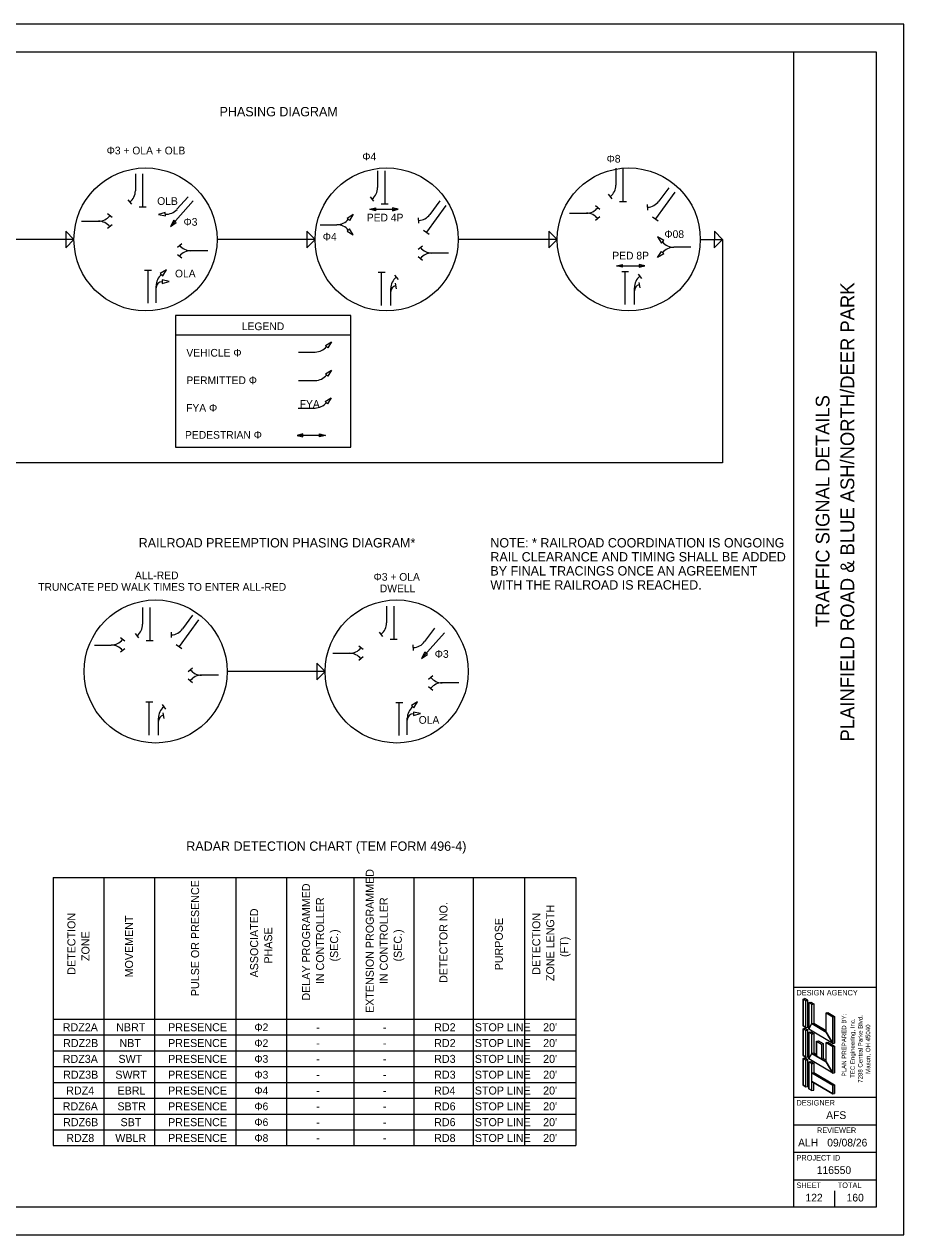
# Model space of a CAD drawing. Extents: x 0 to 34, y 0 to 22.
# Drawn here: x 18.02 to 34, y 0 to 22 of the extents above; entities that cross this region are included whole.
import ezdxf

# ---------------------------------------------------------------- set-up
doc = ezdxf.new("R2010")
doc.units = 0
for name, color, linetype in [('Default', 7, 'Continuous'), ('SG_P_Text', 7, 'Continuous'), ('SH_Border', 7, 'Continuous'), ('SH_Cut_Line', 7, 'Continuous'), ('SH_Data', 7, 'Continuous'), ('SH_Text', 7, 'Continuous')]:
    doc.layers.add(name, color=color, linetype=linetype)

msp = doc.modelspace()

# ---------------------------------------------------------------- linework, layer by layer
at = {"layer": 'SG_P_Text'}
for p, q in [((18.923, 18.089), (17.142, 18.089)), ((23.303, 18.089), (21.522, 18.089)), ((27.704, 18.089), (25.924, 18.089)), ((20.765, 16.356), (23.956, 16.356)), ((23.487, 10.237), (21.706, 10.237)), ((18.544, 6.492), (28.044, 6.492)), ((18.544, 6.492), (18.544, 1.62)), ((19.464, 6.492), (19.464, 1.62)), ((20.384, 6.492), (20.384, 1.62)), ((21.864, 6.492), (21.864, 1.62)), ((22.784, 6.492), (22.784, 1.62)), ((24.005, 6.492), (24.005, 1.62)), ((25.098, 6.492), (25.098, 1.62)), ((26.175, 6.492), (26.175, 1.62)), ((27.11, 6.492), (27.11, 1.62)), ((28.044, 6.492), (28.044, 1.62)), ((18.544, 3.92), (28.044, 3.92)), ((18.544, 3.632), (28.044, 3.632)), ((18.544, 3.345), (28.044, 3.345)), ((18.544, 3.057), (28.044, 3.057)), ((18.544, 2.77), (28.044, 2.77)), ((18.544, 2.482), (28.044, 2.482)), ((18.544, 2.195), (28.044, 2.195)), ((18.544, 1.907), (28.044, 1.907)), ((18.544, 1.62), (28.044, 1.62))]:
    msp.add_line(p, q, dxfattribs=at)
msp.add_lwpolyline([(30.303, 18.089), (30.709, 18.089), (30.709, 14.028), (14.543, 14.028), (14.137, 14.028), (14.137, 18.089), (14.543, 18.089)], dxfattribs=at)
for points in [[(18.923, 18.089), (18.772, 18.241), (18.772, 17.938)], [(23.303, 18.089), (23.152, 18.241), (23.152, 17.938)], [(27.704, 18.089), (27.552, 18.241), (27.552, 17.938)], [(30.709, 18.089), (30.558, 18.241), (30.557, 17.938)], [(23.956, 16.706), (20.767, 16.706), (20.767, 14.311), (23.956, 14.311)], [(23.487, 10.237), (23.336, 10.388), (23.335, 10.085)]]:
    msp.add_lwpolyline(points, close=True, dxfattribs=at)
for centre in [(20.223, 18.089), (24.603, 18.089), (29.003, 18.089), (20.406, 10.237), (24.787, 10.237)]:
    msp.add_circle(centre, 1.3, dxfattribs=at)
at = {"layer": 'SH_Border'}
for p, q in [((32, 0.5), (32, 21.5)), ((32, 4.5), (33.5, 4.5)), ((32, 2.5), (33.5, 2.5)), ((32, 2), (33.5, 2)), ((32, 1.5), (33.5, 1.5)), ((32, 1), (33.5, 1))]:
    msp.add_line(p, q, dxfattribs=at)
msp.add_lwpolyline([(1.5, 21.5), (33.5, 21.5), (33.5, 0.5), (1.5, 0.5)], close=True, dxfattribs=at)
at = {"layer": 'SH_Cut_Line'}
msp.add_lwpolyline([(0, 0), (34, 0), (34, 22), (0, 22)], close=True, dxfattribs=at)
at = {"layer": 'SH_Data'}
for p, q in [((32.75, 3.5), (32.75, 3.5)), ((32.375, 0.675), (32.375, 0.675)), ((32.75, 0.5), (32.75, 0.8))]:
    msp.add_line(p, q, dxfattribs=at)
at = {"layer": 'SH_Text'}
for p, q in [((28.768, 19.381), (28.768, 19.076)), ((28.898, 19.381), (28.898, 18.78)), ((20.039, 19.279), (20.039, 18.974)), ((20.168, 19.279), (20.168, 18.679)), ((24.439, 19.337), (24.439, 19.031)), ((24.569, 19.337), (24.569, 18.736)), ((29.84, 18.948), (29.486, 18.463)), ((29.73, 19.029), (29.549, 18.782)), ((19.972, 18.727), (19.908, 18.807)), ((20.675, 18.325), (21.09, 18.789)), ((20.998, 18.863), (20.794, 18.636)), ((24.372, 18.785), (24.308, 18.865)), ((24.505, 18.736), (24.632, 18.736)), ((25.68, 18.708), (25.326, 18.222)), ((25.569, 18.788), (25.389, 18.542)), ((28.701, 18.829), (28.637, 18.909)), ((28.834, 18.78), (28.961, 18.78)), ((29.35, 18.623), (29.345, 18.725)), ((19.614, 18.487), (19.534, 18.551)), ((20.105, 18.679), (20.232, 18.679)), ((24.3, 18.636), (24.813, 18.636)), ((25.189, 18.382), (25.185, 18.484)), ((27.927, 18.566), (28.233, 18.566)), ((27.927, 18.566), (28.233, 18.566)), ((28.479, 18.633), (28.4, 18.697)), ((28.479, 18.499), (28.4, 18.435)), ((29.435, 18.5), (29.538, 18.426)), ((19.062, 18.42), (19.368, 18.42)), ((19.062, 18.42), (19.368, 18.42)), ((19.614, 18.353), (19.534, 18.289)), ((23.395, 18.357), (23.701, 18.357)), ((23.395, 18.357), (23.701, 18.357)), ((25.275, 18.26), (25.377, 18.185)), ((20.801, 17.95), (20.88, 18.014)), ((21.352, 17.883), (21.047, 17.883)), ((21.352, 17.883), (21.047, 17.883)), ((25.178, 17.909), (25.258, 17.973)), ((25.73, 17.842), (25.424, 17.842)), ((25.73, 17.842), (25.424, 17.842)), ((30.129, 17.946), (29.823, 17.946)), ((30.129, 17.946), (29.823, 17.946)), ((20.801, 17.816), (20.88, 17.752)), ((25.178, 17.776), (25.258, 17.711)), ((28.781, 17.61), (29.294, 17.61)), ((20.204, 17.529), (20.331, 17.529)), ((20.268, 16.928), (20.268, 17.529)), ((24.45, 17.491), (24.577, 17.491)), ((24.513, 16.89), (24.513, 17.491)), ((24.747, 17.442), (24.811, 17.362)), ((28.875, 17.507), (29.001, 17.507)), ((28.938, 16.907), (28.938, 17.507)), ((29.172, 17.459), (29.236, 17.379)), ((20.414, 16.937), (20.414, 17.242)), ((20.415, 17.13), (20.415, 17.207)), ((24.68, 16.89), (24.68, 17.196)), ((24.761, 17.293), (24.778, 17.192)), ((29.105, 16.907), (29.105, 17.212)), ((29.185, 17.309), (29.203, 17.209)), ((24.681, 17.098), (24.681, 17.14)), ((29.105, 17.114), (29.105, 17.157)), ((23.001, 16.043), (23.307, 16.043)), ((23.001, 15.526), (23.307, 15.526)), ((22.996, 15.025), (23.302, 15.025)), ((23.49, 14.528), (22.977, 14.528)), ((20.17, 11.401), (20.17, 11.095)), ((20.3, 11.401), (20.3, 10.8)), ((21.077, 11.258), (20.897, 11.011)), ((24.602, 11.427), (24.602, 11.121)), ((24.732, 11.427), (24.732, 10.826)), ((21.188, 11.177), (20.834, 10.692)), ((25.472, 11.027), (25.292, 10.78)), ((19.845, 10.785), (19.766, 10.849)), ((20.103, 10.849), (20.039, 10.928)), ((20.236, 10.8), (20.363, 10.8)), ((20.697, 10.852), (20.693, 10.954)), ((24.535, 10.875), (24.471, 10.954)), ((24.669, 10.826), (24.796, 10.826)), ((25.239, 10.472), (25.654, 10.937)), ((19.293, 10.718), (19.599, 10.718)), ((19.293, 10.718), (19.599, 10.718)), ((19.845, 10.651), (19.766, 10.587)), ((20.782, 10.729), (20.885, 10.654)), ((23.626, 10.568), (23.931, 10.568)), ((23.626, 10.568), (23.931, 10.568)), ((24.178, 10.635), (24.098, 10.699)), ((25.093, 10.62), (25.088, 10.722)), ((24.178, 10.501), (24.098, 10.437)), ((20.995, 10.237), (21.075, 10.301)), ((21.547, 10.17), (21.242, 10.17)), ((21.547, 10.17), (21.242, 10.17)), ((25.364, 10.098), (25.444, 10.162)), ((20.995, 10.103), (21.075, 10.039)), ((25.364, 9.964), (25.444, 9.9)), ((25.916, 10.031), (25.611, 10.031)), ((25.916, 10.031), (25.611, 10.031)), ((20.227, 9.683), (20.354, 9.683)), ((20.291, 9.082), (20.291, 9.683)), ((20.524, 9.634), (20.588, 9.554)), ((20.538, 9.485), (20.556, 9.384)), ((24.768, 9.676), (24.895, 9.676)), ((24.831, 9.076), (24.831, 9.676)), ((20.457, 9.082), (20.457, 9.388)), ((20.458, 9.29), (20.458, 9.332)), ((24.978, 9.084), (24.978, 9.389)), ((24.979, 9.277), (24.979, 9.355)), ((32.169, 4.285), (32.201, 4.294)), ((32.169, 3.799), (32.169, 4.285)), ((32.223, 4.253), (32.169, 4.285)), ((32.255, 4.261), (32.201, 4.294)), ((32.223, 4.253), (32.255, 4.261)), ((32.223, 3.767), (32.223, 4.253)), ((32.255, 3.775), (32.255, 4.261)), ((32.277, 4.221), (32.309, 4.229)), ((32.331, 4.188), (32.277, 4.221)), ((32.277, 3.735), (32.277, 4.221)), ((32.309, 4.229), (32.363, 4.196)), ((32.331, 4.188), (32.363, 4.196)), ((32.331, 3.837), (32.331, 4.188)), ((32.363, 4.196), (32.363, 3.845)), ((32.587, 4.034), (32.62, 4.042)), ((32.587, 3.683), (32.587, 4.034)), ((32.709, 3.961), (32.587, 4.034)), ((32.62, 4.042), (32.741, 3.97)), ((32.709, 3.961), (32.741, 3.97)), ((32.709, 3.475), (32.709, 3.961)), ((32.741, 3.97), (32.741, 3.484)), ((32.223, 3.767), (32.169, 3.799)), ((32.169, 3.745), (32.201, 3.754)), ((32.169, 3.259), (32.169, 3.745)), ((32.223, 3.713), (32.169, 3.745)), ((32.255, 3.722), (32.201, 3.754)), ((32.223, 3.767), (32.255, 3.775)), ((32.331, 3.837), (32.363, 3.845)), ((32.587, 3.683), (32.331, 3.837)), ((32.363, 3.845), (32.587, 3.711)), ((32.223, 3.713), (32.255, 3.722)), ((32.223, 3.227), (32.223, 3.713)), ((32.255, 3.236), (32.255, 3.722)), ((32.709, 3.475), (32.277, 3.735)), ((32.277, 3.681), (32.309, 3.689)), ((32.277, 3.195), (32.277, 3.681)), ((32.331, 3.648), (32.277, 3.681)), ((32.309, 3.689), (32.363, 3.656)), ((32.331, 3.648), (32.363, 3.656)), ((32.331, 3.297), (32.331, 3.648)), ((32.363, 3.656), (32.363, 3.305)), ((32.415, 3.519), (32.448, 3.527)), ((32.448, 3.527), (32.535, 3.474)), ((32.331, 3.297), (32.363, 3.305)), ((32.363, 3.305), (32.415, 3.274)), ((32.415, 3.519), (32.415, 3.247)), ((32.415, 3.519), (32.503, 3.466)), ((32.503, 3.466), (32.535, 3.474)), ((32.503, 3.466), (32.503, 3.194)), ((32.535, 3.474), (32.535, 3.202)), ((32.587, 3.494), (32.62, 3.502)), ((32.587, 3.143), (32.587, 3.494)), ((32.709, 3.421), (32.587, 3.494)), ((32.62, 3.502), (32.741, 3.43)), ((32.709, 3.475), (32.741, 3.484)), ((32.709, 3.421), (32.741, 3.43)), ((32.709, 2.935), (32.709, 3.421)), ((32.741, 3.43), (32.741, 2.944)), ((32.223, 3.227), (32.169, 3.259)), ((32.169, 3.205), (32.201, 3.215)), ((32.169, 2.719), (32.169, 3.205)), ((32.223, 3.173), (32.169, 3.205)), ((32.255, 3.181), (32.201, 3.215)), ((32.222, 3.173), (32.255, 3.181)), ((32.223, 3.227), (32.255, 3.236)), ((32.223, 2.687), (32.223, 3.173)), ((32.255, 2.695), (32.255, 3.181)), ((32.709, 2.935), (32.277, 3.195)), ((32.277, 3.141), (32.309, 3.151)), ((32.331, 3.108), (32.277, 3.141)), ((32.277, 2.655), (32.277, 3.141)), ((32.309, 3.151), (32.363, 3.116)), ((32.415, 3.247), (32.331, 3.297)), ((32.331, 3.108), (32.363, 3.116)), ((32.331, 2.944), (32.331, 3.108)), ((32.363, 3.116), (32.363, 2.952)), ((32.503, 3.194), (32.535, 3.202)), ((32.587, 3.143), (32.503, 3.194)), ((32.535, 3.202), (32.587, 3.171)), ((32.331, 2.944), (32.363, 2.952)), ((32.331, 2.944), (32.709, 2.717)), ((32.363, 2.952), (32.741, 2.725)), ((32.709, 2.935), (32.741, 2.944)), ((32.223, 2.687), (32.169, 2.719)), ((32.223, 2.687), (32.255, 2.695)), ((32.331, 2.622), (32.277, 2.655)), ((32.331, 2.787), (32.709, 2.56)), ((32.331, 2.622), (32.331, 2.787)), ((32.363, 2.63), (32.363, 2.767)), ((32.709, 2.717), (32.741, 2.725)), ((32.709, 2.56), (32.709, 2.717)), ((32.741, 2.725), (32.741, 2.568)), ((32.331, 2.622), (32.363, 2.63)), ((32.709, 2.56), (32.741, 2.568))]:
    msp.add_line(p, q, dxfattribs=at)
for points in [[(20.581, 18.579), (20.458, 18.54), (20.585, 18.516)], [(23.885, 18.478), (23.996, 18.545), (23.929, 18.434)], [(24.404, 18.61), (24.3, 18.636), (24.404, 18.662)], [(24.709, 18.61), (24.813, 18.636), (24.709, 18.662)], [(20.735, 18.439), (20.675, 18.325), (20.782, 18.397)], [(23.885, 18.236), (23.996, 18.17), (23.929, 18.28)], [(29.639, 18.067), (29.528, 18.134), (29.595, 18.023)], [(29.639, 17.825), (29.528, 17.759), (29.595, 17.87)], [(28.885, 17.584), (28.781, 17.61), (28.885, 17.636)], [(29.19, 17.584), (29.294, 17.61), (29.19, 17.636)], [(20.535, 17.427), (20.602, 17.537), (20.491, 17.471)], [(20.528, 17.29), (20.652, 17.324), (20.526, 17.352)], [(23.491, 16.164), (23.602, 16.23), (23.535, 16.12)], [(23.491, 15.647), (23.602, 15.713), (23.535, 15.603)], [(23.486, 15.146), (23.597, 15.212), (23.53, 15.102)], [(23.081, 14.554), (22.977, 14.528), (23.081, 14.502)], [(23.386, 14.554), (23.49, 14.528), (23.386, 14.502)], [(25.299, 10.586), (25.239, 10.472), (25.346, 10.544)], [(25.099, 9.574), (25.165, 9.685), (25.055, 9.618)], [(25.091, 9.437), (25.216, 9.472), (25.09, 9.5)], [(32.169, 3.799), (32.223, 3.767), (32.223, 4.253), (32.169, 4.285)], [(32.277, 3.735), (32.331, 3.837), (32.331, 4.188), (32.277, 4.221)], [(32.709, 3.475), (32.587, 3.683), (32.587, 4.034), (32.709, 3.961)], [(32.169, 3.259), (32.223, 3.227), (32.223, 3.713), (32.169, 3.745)], [(32.277, 3.735), (32.331, 3.837), (32.587, 3.683), (32.709, 3.475)], [(32.277, 3.195), (32.331, 3.297), (32.331, 3.648), (32.277, 3.681)], [(32.415, 3.247), (32.415, 3.519), (32.503, 3.466), (32.503, 3.194)], [(32.709, 2.935), (32.587, 3.143), (32.587, 3.494), (32.709, 3.421)], [(32.169, 2.719), (32.223, 2.687), (32.223, 3.173), (32.169, 3.205)], [(32.277, 3.195), (32.331, 3.297), (32.587, 3.143), (32.709, 2.935)], [(32.277, 2.655), (32.331, 2.622), (32.331, 3.108), (32.277, 3.141)], [(32.331, 2.787), (32.331, 2.944), (32.709, 2.717), (32.709, 2.56)]]:
    msp.add_lwpolyline(points, close=True, dxfattribs=at)
for centre, radius, start, end in [((19.774, 18.974), 0.265, 308.7993, 0), ((24.174, 19.031), 0.265, 308.7993, 0), ((28.503, 19.076), 0.265, 308.7993, 0), ((29.335, 18.939), 0.265, 272.6906, 323.8913), ((19.368, 18.685), 0.265, 270, 321.2007), ((20.597, 18.812), 0.265, 267.0229, 318.2236), ((25.175, 18.698), 0.265, 272.6906, 323.8913), ((28.233, 18.831), 0.265, 270, 321.2007), ((28.233, 18.301), 0.265, 38.7993, 90), ((19.368, 18.155), 0.265, 38.7993, 90), ((23.701, 18.622), 0.265, 270, 321.2007), ((23.701, 18.092), 0.265, 38.7864, 89.9871), ((29.823, 18.211), 0.265, 218.7993, 270), ((21.047, 18.148), 0.265, 218.7993, 270), ((21.047, 17.618), 0.265, 90, 141.2007), ((25.424, 18.107), 0.265, 218.7993, 270), ((25.424, 17.577), 0.265, 90, 141.2007), ((29.823, 17.681), 0.265, 90, 141.2007), ((20.679, 17.242), 0.265, 128.7993, 180), ((24.945, 17.196), 0.265, 128.7993, 180), ((29.37, 17.212), 0.265, 128.7993, 180), ((20.529, 17.207), 0.113, 91.0096, 180), ((24.793, 17.14), 0.112, 102.9976, 180), ((29.218, 17.157), 0.112, 102.9976, 180), ((23.307, 16.308), 0.265, 270.0129, 321.2136), ((23.307, 15.791), 0.265, 270, 321.2007), ((23.302, 15.29), 0.265, 270, 321.2007), ((19.905, 11.095), 0.265, 308.7993, 0), ((20.683, 11.167), 0.265, 272.6906, 323.8913), ((24.337, 11.121), 0.265, 308.7993, 0), ((19.599, 10.983), 0.265, 270, 321.2007), ((19.599, 10.453), 0.265, 38.7993, 90), ((23.931, 10.833), 0.265, 270, 321.2007), ((23.931, 10.303), 0.265, 38.7993, 90), ((25.078, 10.936), 0.265, 272.6906, 323.8913), ((21.242, 10.435), 0.265, 218.7993, 270), ((21.242, 9.905), 0.265, 90, 141.2007), ((25.611, 10.296), 0.265, 218.7993, 270), ((25.611, 9.766), 0.265, 90, 141.2007), ((20.722, 9.388), 0.265, 128.7993, 180), ((25.243, 9.389), 0.265, 128.7993, 180), ((25.092, 9.355), 0.113, 91.0096, 180), ((20.57, 9.332), 0.112, 102.9976, 180)]:
    msp.add_arc(centre, radius, start, end, dxfattribs=at)

# ---------------------------------------------------------------- texts
at = {"layer": 'Default'}
for s, p in [('PLAN PREPARED BY:', (32.954, 2.88)), ('TEC Engineering, Inc.', (33.11, 2.851)), ('7288 Central Parke Blvd.', (33.25, 2.762)), ('Mason, OH 45040', (33.39, 2.925))]:
    msp.add_text(s, height=0.08, rotation=90, dxfattribs=at).set_placement(p)
at = {"layer": 'SG_P_Text'}
for s, height, p in [('PHASING DIAGRAM', 0.17, (21.568, 20.326)), ('Φ3 + OLA + OLB', 0.14, (19.516, 19.634)), ('Φ4', 0.14, (24.161, 19.525)), ('Φ8', 0.14, (28.6, 19.485)), ('OLB', 0.14, (20.435, 18.716)), ('PED 4P', 0.14, (24.243, 18.417)), ('Φ3', 0.14, (20.913, 18.337)), ('Φ4', 0.14, (23.443, 18.068)), ('Φ08', 0.14, (29.65, 18.115)), ('PED 8P', 0.14, (28.704, 17.725)), ('OLA', 0.14, (20.758, 17.399)), ('LEGEND', 0.14, (21.973, 16.44)), ('VEHICLE Φ', 0.14, (20.965, 15.959)), ('PERMITTED Φ', 0.14, (20.965, 15.459)), ('FYA Φ', 0.14, (20.96, 14.958)), ('FYA', 0.14, (23.024, 15.029)), ('PEDESTRIAN Φ', 0.14, (20.94, 14.467)), ('RAILROAD PREEMPTION PHASING DIAGRAM*', 0.17, (20.098, 12.491)), ('NOTE: * RAILROAD COORDINATION IS ONGOING', 0.17, (26.488, 12.491)), ('RAIL CLEARANCE AND TIMING SHALL BE ADDED', 0.17, (26.488, 12.236)), ('BY FINAL TRACINGS ONCE AN AGREEMENT ', 0.17, (26.488, 11.981)), ('ALL-RED', 0.14, (20.031, 11.914)), ('Φ3 + OLA', 0.14, (24.366, 11.886)), ('WITH THE RAILROAD IS REACHED.', 0.17, (26.488, 11.726)), ('TRUNCATE PED WALK TIMES TO ENTER ALL-RED', 0.14, (18.273, 11.704)), ('DWELL', 0.14, (24.48, 11.676)), ('Φ3', 0.14, (25.477, 10.485)), ('OLA', 0.14, (25.186, 9.287)), ('RADAR DETECTION CHART (TEM FORM 496-4)', 0.17, (20.963, 6.978)), ('RDZ2A', 0.1454, (18.719, 3.699)), ('NBRT', 0.1454, (19.69, 3.699)), ('PRESENCE', 0.1454, (20.633, 3.699)), ('Φ2', 0.14, (22.2, 3.701)), ('-', 0.145, (23.326, 3.699)), ('-', 0.145, (24.537, 3.699)), ('RD2', 0.1454, (25.468, 3.699)), ('STOP LINE', 0.1454, (26.206, 3.699)), ("20'", 0.1454, (27.447, 3.699)), ('RDZ2B', 0.1454, (18.726, 3.412)), ('NBT', 0.1454, (19.749, 3.412)), ('PRESENCE', 0.1454, (20.633, 3.412)), ('Φ2', 0.14, (22.2, 3.413)), ('RD2', 0.1454, (25.468, 3.412)), ('STOP LINE', 0.1454, (26.206, 3.412)), ("20'", 0.1454, (27.447, 3.412)), ('-', 0.145, (23.326, 3.412)), ('-', 0.145, (24.537, 3.412)), ('RDZ3A', 0.1454, (18.719, 3.124)), ('SWT', 0.1454, (19.731, 3.124)), ('PRESENCE', 0.1454, (20.633, 3.124)), ('Φ3', 0.14, (22.2, 3.126)), ('-', 0.145, (23.326, 3.124)), ('-', 0.145, (24.537, 3.124)), ('RD3', 0.1454, (25.468, 3.124)), ('STOP LINE', 0.1454, (26.206, 3.124)), ("20'", 0.1454, (27.447, 3.124)), ('RDZ3B', 0.1454, (18.726, 2.837)), ('SWRT', 0.1454, (19.674, 2.837)), ('PRESENCE', 0.1454, (20.633, 2.837)), ('Φ3', 0.14, (22.2, 2.839)), ('-', 0.145, (23.326, 2.837)), ('-', 0.145, (24.537, 2.837)), ('RD3', 0.1454, (25.468, 2.837)), ('STOP LINE', 0.1454, (26.206, 2.837)), ("20'", 0.1454, (27.447, 2.837)), ('RDZ4', 0.1454, (18.782, 2.549)), ('EBRL', 0.1454, (19.714, 2.549)), ('PRESENCE', 0.1454, (20.633, 2.549)), ('Φ4', 0.14, (22.2, 2.551)), ('RD4', 0.1454, (25.465, 2.549)), ('STOP LINE', 0.1454, (26.206, 2.549)), ("20'", 0.1454, (27.447, 2.549)), ('-', 0.145, (23.326, 2.549)), ('-', 0.145, (24.537, 2.549)), ('RDZ6A', 0.1454, (18.719, 2.262)), ('SBTR', 0.1454, (19.712, 2.262)), ('PRESENCE', 0.1454, (20.633, 2.262)), ('Φ6', 0.14, (22.2, 2.264)), ('-', 0.145, (23.326, 2.262)), ('-', 0.145, (24.537, 2.262)), ('RD6', 0.1454, (25.467, 2.262)), ('STOP LINE', 0.1454, (26.206, 2.262)), ("20'", 0.1454, (27.447, 2.262)), ('RDZ6B', 0.1454, (18.726, 1.974)), ('SBT', 0.1454, (19.769, 1.974)), ('PRESENCE', 0.1454, (20.633, 1.974)), ('Φ6', 0.14, (22.2, 1.976)), ('-', 0.145, (23.326, 1.974)), ('-', 0.145, (24.537, 1.974)), ('RD6', 0.1454, (25.467, 1.974)), ('STOP LINE', 0.1454, (26.206, 1.974)), ("20'", 0.1454, (27.447, 1.974)), ('RDZ8', 0.1454, (18.783, 1.687)), ('WBLR', 0.1454, (19.673, 1.687)), ('PRESENCE', 0.1454, (20.633, 1.687)), ('Φ8', 0.14, (22.2, 1.689)), ('RD8', 0.1454, (25.467, 1.687)), ('STOP LINE', 0.1454, (26.206, 1.687)), ("20'", 0.1454, (27.447, 1.687)), ('-', 0.145, (23.326, 1.687)), ('-', 0.145, (24.537, 1.687))]:
    msp.add_text(s, height=height, dxfattribs=at).set_placement(p)
for s, height, p in [('EXTENSION PROGRAMMED', 0.14545, (24.37, 4.032)), ('PULSE OR PRESENCE', 0.14545, (21.196, 4.337)), ('DELAY PROGRAMMED', 0.14545, (23.213, 4.256)), (' IN CONTROLLER', 0.14545, (23.467, 4.501)), (' IN CONTROLLER', 0.14545, (24.624, 4.501)), ('DETECTOR NO.', 0.14545, (25.709, 4.577)), ('ZONE LENGTH', 0.14545, (27.649, 4.611)), ('DETECTION', 0.1454, (18.949, 4.726)), ('MOVEMENT', 0.1454, (19.996, 4.678)), ('ASSOCIATED', 0.1454, (22.269, 4.677)), ('PURPOSE', 0.1454, (26.715, 4.806)), ('DETECTION', 0.1454, (27.395, 4.726)), ('ZONE', 0.1454, (19.204, 4.975)), ('PHASE', 0.1454, (22.524, 4.929)), ('(SEC.)', 0.1454, (23.722, 4.967)), ('(SEC.)', 0.1454, (24.879, 4.967)), ('(FT)', 0.1454, (27.904, 5.049))]:
    msp.add_text(s, height=height, rotation=90, dxfattribs=at).set_placement(p)
at = {"layer": 'SH_Data'}
for s, p in [('PLAINFIELD ROAD & BLUE ASH/NORTH/DEER PARK', (33.1, 8.965)), ('TRAFFIC SIGNAL DETAILS', (32.65, 11.043))]:
    msp.add_text(s, height=0.25, rotation=90, dxfattribs=at).set_placement(p)
for s, height, p in [('DESIGN AGENCY', 0.1, (32.05, 4.35)), ('DESIGNER', 0.1, (32.05, 2.35)), ('AFS', 0.14, (32.59, 2.105)), ('REVIEWER', 0.1, (32.422, 1.85)), ('ALH', 0.14, (32.08, 1.605)), ('09/08/26', 0.14, (32.609, 1.605)), ('PROJECT ID', 0.1, (32.05, 1.35)), ('116550', 0.14, (32.419, 1.105)), ('SHEET', 0.1, (32.05, 0.85)), ('TOTAL', 0.1, (32.8, 0.85)), ('122', 0.14, (32.214, 0.605)), ('160', 0.14, (32.961, 0.605))]:
    msp.add_text(s, height=height, dxfattribs=at).set_placement(p)

doc.saveas('drawing.dxf')
